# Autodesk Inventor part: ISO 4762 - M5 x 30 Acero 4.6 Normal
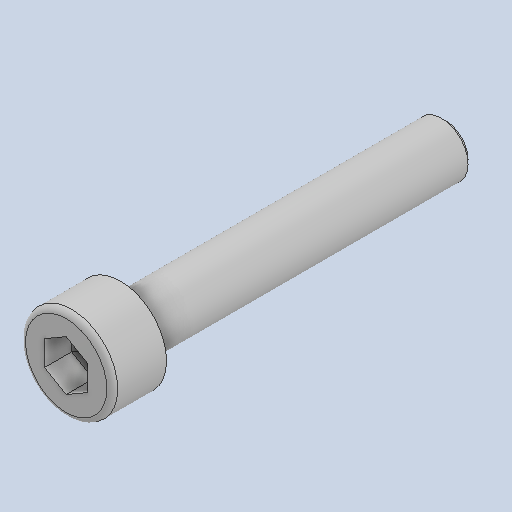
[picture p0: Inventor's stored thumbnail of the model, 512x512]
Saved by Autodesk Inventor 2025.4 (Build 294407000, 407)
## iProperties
Created: 2026-09
Part Number: ISO 4762 - M5 x 30 Acero 4.6 Normal
Material: Generic
Description: Tornillo de cabeza hexagonal hueca ISO 4762 - M5 x 30
Document SubType Name: Modeling
Designer: AdminForWorker
Density: 1 g/cm^3
Appearance: Default
Title: Tornillo de cabeza hexagonal hueca ISO 4762 - M5 x 30 Acero 4.6 Normal v1
Author: AdminForWorker
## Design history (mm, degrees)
feature "Body1"
body "Solid1"
